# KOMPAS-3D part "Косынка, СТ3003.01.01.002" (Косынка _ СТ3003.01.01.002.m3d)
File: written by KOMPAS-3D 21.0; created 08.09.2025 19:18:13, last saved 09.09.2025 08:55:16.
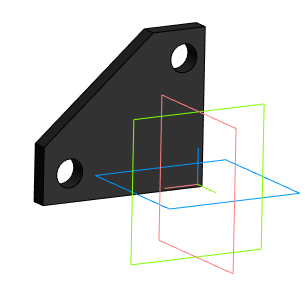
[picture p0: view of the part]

Document properties: Полное имя файла: C:\Users\1\Yandex.Disk\Документы\Новая папка\Стапель №2\Стапель _ СТ3003.00.00.000\Опора _ СТ3003.01.00.000\3D\Кронштейн _ СТ3003.01.01.000\Косынка _ СТ3003.01.01.002.m3d

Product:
- Part/product: Косынка  | designation СТ3003.01.01.002
    Материал: Лист$dБ-ПН-НО-6 ГОСТ 19903-2015;Ст3сп ГОСТ 14637-89$ (density 7850 kg/m3)
    Масса: 0.116828
    Форматы листов документа: A4

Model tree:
1. Эскиз:1
2. Элемент выдавливания:1  (labels: Лист$dБ-ПН-НО-6 ГОСТ 19903-2015;Ст3сп ГОСТ 14637-89$)
     Расстояние 1 = 6

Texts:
  СТ3003.01.01.002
